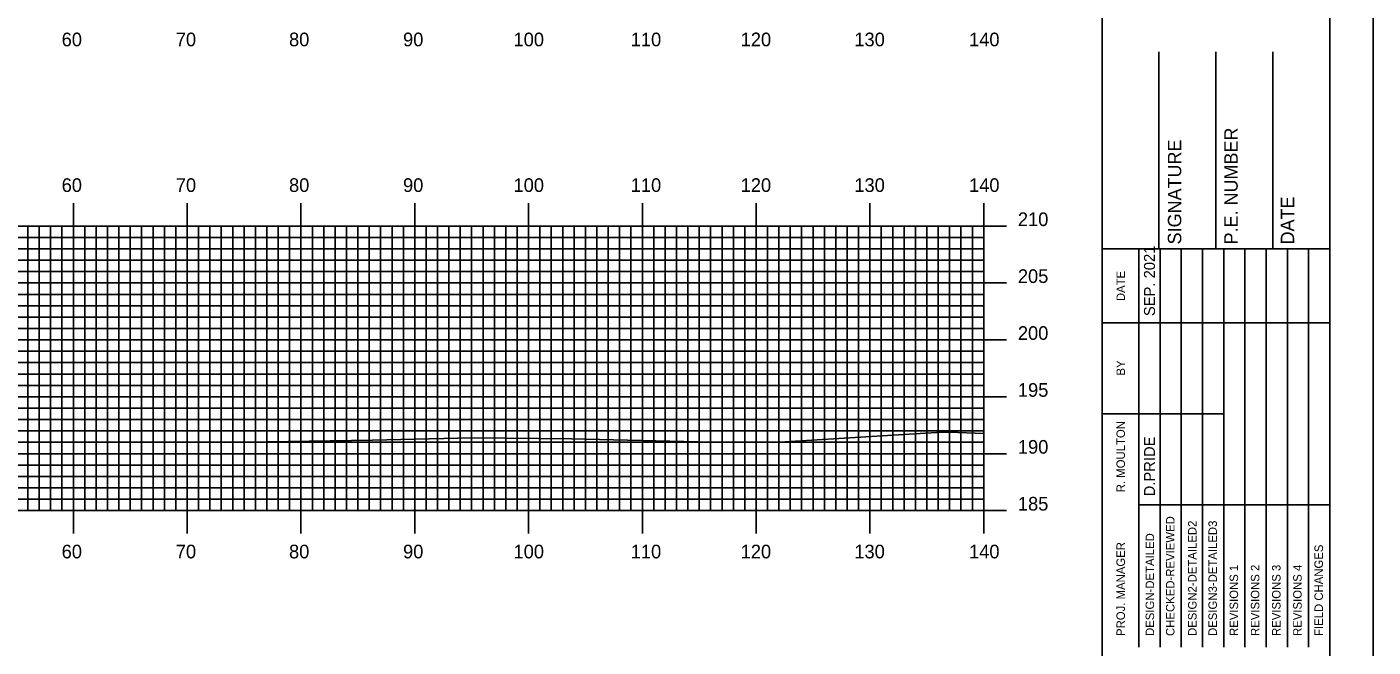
# Model space of a CAD drawing. Extents: x 1814915 to 1815259, y 442591 to 442811.
# Drawn here: x 1815136.9 to 1815255.2, y 442686.7 to 442741.2 of the extents above; entities that cross this region are included whole.
import ezdxf

# ---------------------------------------------------------------- set-up
doc = ezdxf.new("R2010")
doc.units = 0
for name, color, linetype in [('BORDER', 7, 'Continuous'), ('H_V ANNOTATION', 7, 'Continuous'), ('MAJOR', 7, 'Continuous'), ('MINOR', 7, 'Continuous'), ('PLOT BOUNDARY', 7, 'Continuous'), ('S_Roadway_Centerline', 7, 'Continuous')]:
    doc.layers.add(name, color=color, linetype=linetype)

msp = doc.modelspace()

# ---------------------------------------------------------------- linework, layer by layer
at = {"layer": 'BORDER'}
for p, q in [((1815231.42, 442596.67), (1815231.42, 442806.67)), ((1815236.42, 442721.67), (1815236.42, 442738.97)), ((1815241.42, 442721.67), (1815241.42, 442738.97)), ((1815246.42, 442721.67), (1815246.42, 442738.97)), ((1815231.42, 442721.67), (1815251.42, 442721.67))]:
    msp.add_line(p, q, dxfattribs=at)
msp.add_lwpolyline([(1814931.42, 442596.67), (1815251.42, 442596.67), (1815251.42, 442806.67), (1814931.42, 442806.67)], close=True, dxfattribs=at)
for points in [[(1815234.65, 442715.17), (1815234.65, 442721.67)], [(1815236.52, 442686.68), (1815236.52, 442721.67)], [(1815238.38, 442721.67), (1815238.38, 442686.68)], [(1815240.24, 442686.68), (1815240.24, 442721.67)], [(1815242.11, 442686.68), (1815242.11, 442721.67)], [(1815243.97, 442686.68), (1815243.97, 442721.67)], [(1815245.83, 442686.68), (1815245.83, 442721.67)], [(1815247.7, 442686.68), (1815247.7, 442721.67)], [(1815249.56, 442686.68), (1815249.56, 442721.67)], [(1815234.65, 442686.68), (1815234.65, 442720.26)], [(1815231.42, 442715.17), (1815251.42, 442715.17)], [(1815231.42, 442707.17), (1815234.65, 442707.17)], [(1815234.65, 442707.17), (1815242.1, 442707.17)], [(1815234.65, 442699.17), (1815251.42, 442699.17)]]:
    msp.add_lwpolyline(points, dxfattribs=at)
at = {"layer": 'MAJOR'}
for p, q in [((1815141.02, 442725.67), (1815141.02, 442723.67)), ((1815151.02, 442725.67), (1815151.02, 442723.67)), ((1815161.02, 442725.67), (1815161.02, 442723.67)), ((1815171.02, 442725.67), (1815171.02, 442723.67)), ((1815181.02, 442725.67), (1815181.02, 442723.67)), ((1815191.02, 442725.67), (1815191.02, 442723.67)), ((1815201.02, 442725.67), (1815201.02, 442723.67)), ((1815211.02, 442725.67), (1815211.02, 442723.67)), ((1815221.02, 442725.67), (1815221.02, 442723.67)), ((1814941.02, 442723.67), (1815221.02, 442723.67)), ((1814941.02, 442723.67), (1815221.02, 442723.67)), ((1815141.02, 442698.67), (1815141.02, 442723.67)), ((1815151.02, 442698.67), (1815151.02, 442723.67)), ((1815161.02, 442698.67), (1815161.02, 442723.67)), ((1815171.02, 442698.67), (1815171.02, 442723.67)), ((1815181.02, 442698.67), (1815181.02, 442723.67)), ((1815191.02, 442698.67), (1815191.02, 442723.67)), ((1815201.02, 442698.67), (1815201.02, 442723.67)), ((1815211.02, 442698.67), (1815211.02, 442723.67)), ((1815223.02, 442723.67), (1815219.02, 442723.67)), ((1815221.02, 442698.67), (1815221.02, 442723.67)), ((1815221.02, 442698.67), (1815221.02, 442723.67)), ((1814941.02, 442718.67), (1815221.02, 442718.67)), ((1815223.02, 442718.67), (1815219.02, 442718.67)), ((1814941.02, 442713.67), (1815221.02, 442713.67)), ((1815223.02, 442713.67), (1815219.02, 442713.67)), ((1814941.02, 442708.67), (1815221.02, 442708.67)), ((1815223.02, 442708.67), (1815219.02, 442708.67)), ((1814941.02, 442703.67), (1815221.02, 442703.67)), ((1815223.02, 442703.67), (1815219.02, 442703.67)), ((1814941.02, 442698.67), (1815221.02, 442698.67)), ((1814941.02, 442698.67), (1815221.02, 442698.67)), ((1815141.02, 442696.66), (1815141.02, 442698.67)), ((1815151.02, 442696.66), (1815151.02, 442698.67)), ((1815161.02, 442696.66), (1815161.02, 442698.67)), ((1815171.02, 442696.66), (1815171.02, 442698.67)), ((1815181.02, 442696.66), (1815181.02, 442698.67)), ((1815191.02, 442696.66), (1815191.02, 442698.67)), ((1815201.02, 442696.66), (1815201.02, 442698.67)), ((1815211.02, 442696.66), (1815211.02, 442698.67)), ((1815223.02, 442698.67), (1815219.02, 442698.67)), ((1815221.02, 442696.66), (1815221.02, 442698.67))]:
    msp.add_line(p, q, dxfattribs=at)
at = {"layer": 'MINOR'}
for p, q in [((1815137.02, 442698.67), (1815137.02, 442723.67)), ((1815138.02, 442698.67), (1815138.02, 442723.67)), ((1815139.02, 442698.67), (1815139.02, 442723.67)), ((1815140.02, 442698.67), (1815140.02, 442723.67)), ((1815142.02, 442698.67), (1815142.02, 442723.67)), ((1815143.02, 442698.67), (1815143.02, 442723.67)), ((1815144.02, 442698.67), (1815144.02, 442723.67)), ((1815145.02, 442698.67), (1815145.02, 442723.67)), ((1815146.02, 442698.67), (1815146.02, 442723.67)), ((1815147.02, 442698.67), (1815147.02, 442723.67)), ((1815148.02, 442698.67), (1815148.02, 442723.67)), ((1815149.02, 442698.67), (1815149.02, 442723.67)), ((1815150.02, 442698.67), (1815150.02, 442723.67)), ((1815152.02, 442698.67), (1815152.02, 442723.67)), ((1815153.02, 442698.67), (1815153.02, 442723.67)), ((1815154.02, 442698.67), (1815154.02, 442723.67)), ((1815155.02, 442698.67), (1815155.02, 442723.67)), ((1815156.02, 442698.67), (1815156.02, 442723.67)), ((1815157.02, 442698.67), (1815157.02, 442723.67)), ((1815158.02, 442698.67), (1815158.02, 442723.67)), ((1815159.02, 442698.67), (1815159.02, 442723.67)), ((1815160.02, 442698.67), (1815160.02, 442723.67)), ((1815162.02, 442698.67), (1815162.02, 442723.67)), ((1815163.02, 442698.67), (1815163.02, 442723.67)), ((1815164.02, 442698.67), (1815164.02, 442723.67)), ((1815165.02, 442698.67), (1815165.02, 442723.67)), ((1815166.02, 442698.67), (1815166.02, 442723.67)), ((1815167.02, 442698.67), (1815167.02, 442723.67)), ((1815168.02, 442698.67), (1815168.02, 442723.67)), ((1815169.02, 442698.67), (1815169.02, 442723.67)), ((1815170.02, 442698.67), (1815170.02, 442723.67)), ((1815172.02, 442698.67), (1815172.02, 442723.67)), ((1815173.02, 442698.67), (1815173.02, 442723.67)), ((1815174.02, 442698.67), (1815174.02, 442723.67)), ((1815175.02, 442698.67), (1815175.02, 442723.67)), ((1815176.02, 442698.67), (1815176.02, 442723.67)), ((1815177.02, 442698.67), (1815177.02, 442723.67)), ((1815178.02, 442698.67), (1815178.02, 442723.67)), ((1815179.02, 442698.67), (1815179.02, 442723.67)), ((1815180.02, 442698.67), (1815180.02, 442723.67)), ((1815182.02, 442698.67), (1815182.02, 442723.67)), ((1815183.02, 442698.67), (1815183.02, 442723.67)), ((1815184.02, 442698.67), (1815184.02, 442723.67)), ((1815185.02, 442698.67), (1815185.02, 442723.67)), ((1815186.02, 442698.67), (1815186.02, 442723.67)), ((1815187.02, 442698.67), (1815187.02, 442723.67)), ((1815188.02, 442698.67), (1815188.02, 442723.67)), ((1815189.02, 442698.67), (1815189.02, 442723.67)), ((1815190.02, 442698.67), (1815190.02, 442723.67)), ((1815192.02, 442698.67), (1815192.02, 442723.67)), ((1815193.02, 442698.67), (1815193.02, 442723.67)), ((1815194.02, 442698.67), (1815194.02, 442723.67)), ((1815195.02, 442698.67), (1815195.02, 442723.67)), ((1815196.02, 442698.67), (1815196.02, 442723.67)), ((1815197.02, 442698.67), (1815197.02, 442723.67)), ((1815198.02, 442698.67), (1815198.02, 442723.67)), ((1815199.02, 442698.67), (1815199.02, 442723.67)), ((1815200.02, 442698.67), (1815200.02, 442723.67)), ((1815202.02, 442698.67), (1815202.02, 442723.67)), ((1815203.02, 442698.67), (1815203.02, 442723.67)), ((1815204.02, 442698.67), (1815204.02, 442723.67)), ((1815205.02, 442698.67), (1815205.02, 442723.67)), ((1815206.02, 442698.67), (1815206.02, 442723.67)), ((1815207.02, 442698.67), (1815207.02, 442723.67)), ((1815208.02, 442698.67), (1815208.02, 442723.67)), ((1815209.02, 442698.67), (1815209.02, 442723.67)), ((1815210.02, 442698.67), (1815210.02, 442723.67)), ((1815212.02, 442698.67), (1815212.02, 442723.67)), ((1815213.02, 442698.67), (1815213.02, 442723.67)), ((1815214.02, 442698.67), (1815214.02, 442723.67)), ((1815215.02, 442698.67), (1815215.02, 442723.67)), ((1815216.02, 442698.67), (1815216.02, 442723.67)), ((1815217.02, 442698.67), (1815217.02, 442723.67)), ((1815218.02, 442698.67), (1815218.02, 442723.67)), ((1815219.02, 442698.67), (1815219.02, 442723.67)), ((1815220.02, 442698.67), (1815220.02, 442723.67)), ((1814941.02, 442722.67), (1815221.02, 442722.67)), ((1815221.02, 442722.67), (1815219.02, 442722.67)), ((1814941.02, 442721.67), (1815221.02, 442721.67)), ((1815221.02, 442721.67), (1815219.02, 442721.67)), ((1814941.02, 442720.67), (1815221.02, 442720.67)), ((1815221.02, 442720.67), (1815219.02, 442720.67)), ((1814941.02, 442719.67), (1815221.02, 442719.67)), ((1815221.02, 442719.67), (1815219.02, 442719.67)), ((1814941.02, 442717.67), (1815221.02, 442717.67)), ((1814941.02, 442716.67), (1815221.02, 442716.67)), ((1815221.02, 442717.67), (1815219.02, 442717.67)), ((1815221.02, 442716.67), (1815219.02, 442716.67)), ((1814941.02, 442715.67), (1815221.02, 442715.67)), ((1815221.02, 442715.67), (1815219.02, 442715.67)), ((1814941.02, 442714.67), (1815221.02, 442714.67)), ((1815221.02, 442714.67), (1815219.02, 442714.67)), ((1814941.02, 442712.67), (1815221.02, 442712.67)), ((1815221.02, 442712.67), (1815219.02, 442712.67)), ((1814941.02, 442711.67), (1815221.02, 442711.67)), ((1814941.02, 442710.67), (1815221.02, 442710.67)), ((1815221.02, 442711.67), (1815219.02, 442711.67)), ((1815221.02, 442710.67), (1815219.02, 442710.67)), ((1814941.02, 442709.67), (1815221.02, 442709.67)), ((1815221.02, 442709.67), (1815219.02, 442709.67)), ((1814941.02, 442707.67), (1815221.02, 442707.67)), ((1815221.02, 442707.67), (1815219.02, 442707.67)), ((1814941.02, 442706.67), (1815221.02, 442706.67)), ((1815221.02, 442706.67), (1815219.02, 442706.67)), ((1814941.02, 442705.67), (1815221.02, 442705.67)), ((1815221.02, 442705.67), (1815219.02, 442705.67)), ((1814941.02, 442704.67), (1815221.02, 442704.67)), ((1815221.02, 442704.67), (1815219.02, 442704.67)), ((1814941.02, 442702.67), (1815221.02, 442702.67)), ((1815221.02, 442702.67), (1815219.02, 442702.67)), ((1814941.02, 442701.67), (1815221.02, 442701.67)), ((1815221.02, 442701.67), (1815219.02, 442701.67)), ((1814941.02, 442700.67), (1815221.02, 442700.67)), ((1815221.02, 442700.67), (1815219.02, 442700.67)), ((1814941.02, 442699.67), (1815221.02, 442699.67)), ((1815221.02, 442699.67), (1815219.02, 442699.67))]:
    msp.add_line(p, q, dxfattribs=at)
at = {"layer": 'PLOT BOUNDARY'}
msp.add_lwpolyline([(1814915.23, 442590.55), (1815255.23, 442590.55), (1815255.23, 442810.55), (1814915.23, 442810.55)], close=True, dxfattribs=at)
at = {"layer": 'S_Roadway_Centerline'}
msp.add_lwpolyline([(1815134.62, 442704.7), (1815138.79, 442704.69), (1815148.3, 442704.68), (1815150.87, 442704.72), (1815154.34, 442704.66), (1815167.31, 442704.85), (1815176.07, 442705.07), (1815184.79, 442704.97), (1815197.13, 442704.68), (1815200.25, 442704.72), (1815202.57, 442704.65), (1815215.91, 442705.47), (1815217.4, 442705.56), (1815217.65, 442705.55), (1815218.02, 442705.55), (1815221.02, 442705.44)], dxfattribs=at)

# ---------------------------------------------------------------- texts
at = {"layer": 'BORDER'}
for s, height, p in [('P.E. NUMBER', 1.1811, (1815243.34, 442722.06)), ('SIGNATURE', 1.181, (1815238.38, 442722.06)), ('DATE', 1.181, (1815248.3, 442722.06)), ('SEP. 2021', 0.969, (1815236.07, 442715.76)), ('DATE', 0.743, (1815233.43, 442717.08)), ('BY', 0.743, (1815233.43, 442710.54)), ('R. MOULTON', 0.745, (1815233.43, 442700.28)), ('D.PRIDE', 0.969, (1815236.07, 442699.92)), ('CHECKED-REVIEWED', 0.7455, (1815237.78, 442687.65)), ('DESIGN2-DETAILED2', 0.7455, (1815239.72, 442687.65)), ('DESIGN3-DETAILED3', 0.7455, (1815241.51, 442687.65)), ('DESIGN-DETAILED', 0.7455, (1815235.99, 442687.65)), ('PROJ. MANAGER', 0.7455, (1815233.43, 442687.65)), ('FIELD CHANGES', 0.7455, (1815250.83, 442687.65)), ('REVISIONS 1', 0.7455, (1815243.37, 442687.65)), ('REVISIONS 2', 0.7455, (1815245.24, 442687.65)), ('REVISIONS 3', 0.7455, (1815247.1, 442687.65)), ('REVISIONS 4', 0.7455, (1815248.96, 442687.65))]:
    msp.add_text(s, height=height, rotation=90, dxfattribs=at).set_placement(p)
at = {"layer": 'H_V ANNOTATION'}
for s, p in [('60', (1815139.99, 442739.47)), ('70', (1815150.02, 442739.47)), ('80', (1815159.97, 442739.47)), ('90', (1815169.99, 442739.47)), ('100', (1815179.7, 442739.47)), ('110', (1815190, 442739.47)), ('120', (1815199.66, 442739.47)), ('130', (1815209.65, 442739.47)), ('140', (1815219.73, 442739.47)), ('60', (1815139.99, 442726.67)), ('70', (1815150.02, 442726.67)), ('80', (1815159.97, 442726.67)), ('90', (1815169.99, 442726.67)), ('100', (1815179.7, 442726.67)), ('110', (1815190, 442726.67)), ('120', (1815199.66, 442726.67)), ('130', (1815209.65, 442726.67)), ('140', (1815219.73, 442726.67)), ('210', (1815224.02, 442723.67)), ('205', (1815224.02, 442718.67)), ('200', (1815224.02, 442713.67)), ('195', (1815224.02, 442708.67)), ('190', (1815224.02, 442703.67)), ('185', (1815224.02, 442698.67)), ('60', (1815139.99, 442694.47)), ('70', (1815150.02, 442694.47)), ('80', (1815159.97, 442694.47)), ('90', (1815169.99, 442694.47)), ('100', (1815179.7, 442694.47)), ('110', (1815190, 442694.47)), ('120', (1815199.66, 442694.47)), ('130', (1815209.65, 442694.47)), ('140', (1815219.73, 442694.47))]:
    msp.add_text(s, height=1.2, dxfattribs=at).set_placement(p)

doc.saveas('drawing.dxf')
